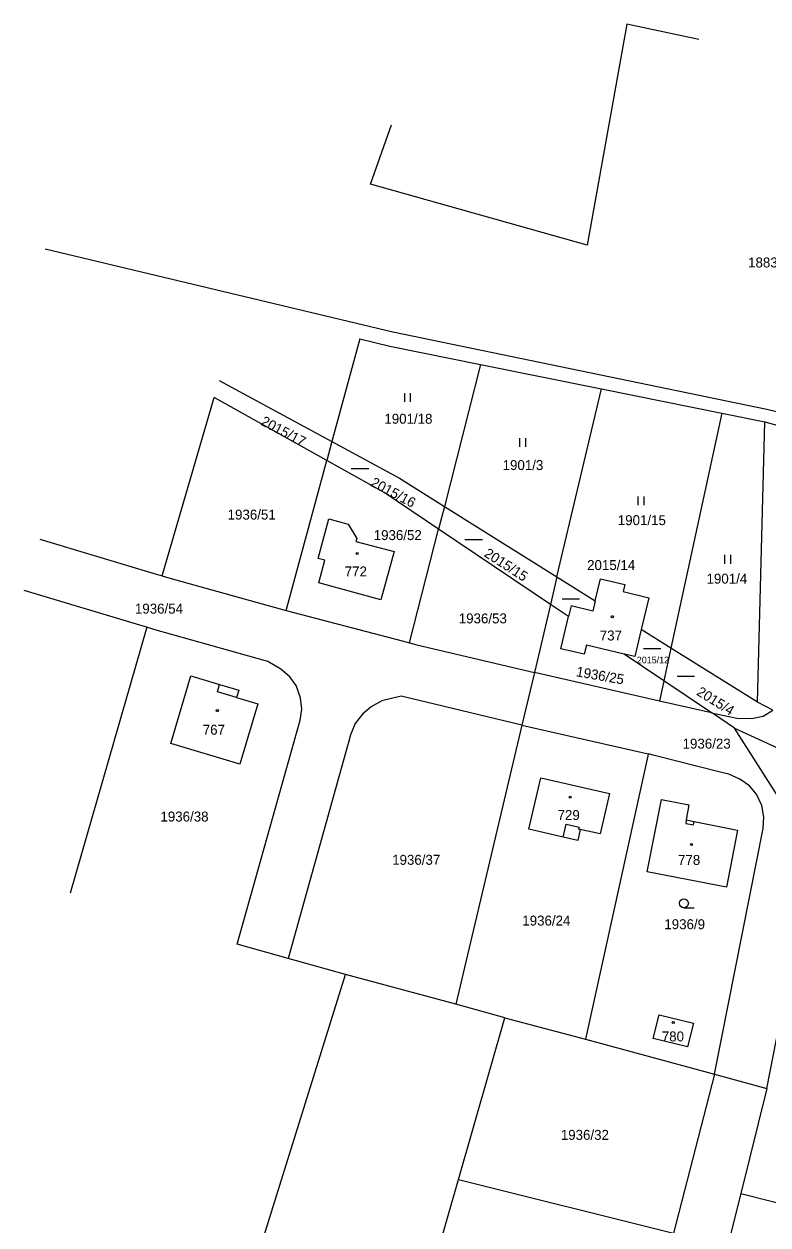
# Model space of a CAD drawing. Extents: x -793666 to -785424, y -1118958 to -1108761.
# Drawn here: x -788618 to -788490.9, y -1116664.5 to -1116459.4 of the extents above; entities that cross this region are included whole.
import ezdxf

# ---------------------------------------------------------------- set-up
doc = ezdxf.new("R2010")
doc.units = 0
for name, color, linetype in [('Hranice parcel', 7, 'Continuous'), ('Parcelní čísla', 7, 'Continuous'), ('Vnitřní kresba', 7, 'Continuous'), ('Značky budov', 7, 'Continuous'), ('Značky kultur', 7, 'Continuous')]:
    doc.layers.add(name, color=color, linetype=linetype)

msp = doc.modelspace()

# ---------------------------------------------------------------- linework, layer by layer
at = {"layer": 'Hranice parcel'}
for p, q in [((-788560.67, -1116513.12), (-788565.43, -1116530.67)), ((-788540.02, -1116517.5), (-788546.21, -1116541.74)), ((-788540.02, -1116517.5), (-788519.4, -1116521.68)), ((-788584.68, -1116520.22), (-788565.43, -1116530.67)), ((-788594.39, -1116553.63), (-788585.54, -1116523.16)), ((-788566.3, -1116533.9), (-788585.54, -1116523.16)), ((-788526.98, -1116553.77), (-788519.4, -1116521.68)), ((-788519.4, -1116521.68), (-788498.83, -1116525.84)), ((-788498.83, -1116525.84), (-788507.51, -1116565.95)), ((-788498.83, -1116525.84), (-788491.48, -1116527.33)), ((-788492.74, -1116575.19), (-788491.48, -1116527.33)), ((-788491.48, -1116527.33), (-788478.73, -1116530.8)), ((-788565.43, -1116530.67), (-788566.3, -1116533.9)), ((-788573.26, -1116559.54), (-788566.3, -1116533.9)), ((-788546.21, -1116541.74), (-788547.2, -1116545.62)), ((-788546.21, -1116541.74), (-788526.98, -1116553.77)), ((-788552.16, -1116565.07), (-788547.2, -1116545.62)), ((-788528.09, -1116558.48), (-788547.2, -1116545.62)), ((-788526.98, -1116553.77), (-788528.09, -1116558.48)), ((-788526.98, -1116553.77), (-788520.44, -1116557.86)), ((-788520.44, -1116557.86), (-788519.55, -1116554.11)), ((-788520.44, -1116557.86), (-788520.86, -1116559.64)), ((-788511.28, -1116557.35), (-788512.57, -1116562.78)), ((-788528.09, -1116558.48), (-788530.84, -1116570.12)), ((-788524.99, -1116560.57), (-788528.09, -1116558.48)), ((-788524.56, -1116558.76), (-788524.99, -1116560.57)), ((-788520.86, -1116559.64), (-788524.56, -1116558.76)), ((-788597.04, -1116562.39), (-788610.11, -1116607.83)), ((-788526.29, -1116566.06), (-788524.99, -1116560.57)), ((-788507.51, -1116565.95), (-788512.57, -1116562.78)), ((-788552.16, -1116565.07), (-788550.89, -1116565.39)), ((-788550.89, -1116565.39), (-788530.84, -1116570.12)), ((-788515.48, -1116566.97), (-788521.93, -1116565.45)), ((-788507.51, -1116565.95), (-788508.72, -1116571.52)), ((-788492.74, -1116575.19), (-788507.51, -1116565.95)), ((-788508.72, -1116571.52), (-788515.48, -1116566.97)), ((-788530.84, -1116570.12), (-788532.99, -1116579.1)), ((-788509.48, -1116575.03), (-788530.84, -1116570.12)), ((-788508.72, -1116571.52), (-788509.48, -1116575.03)), ((-788500.6, -1116576.98), (-788508.72, -1116571.52)), ((-788532.99, -1116579.1), (-788553.61, -1116574.15)), ((-788500.6, -1116576.98), (-788509.48, -1116575.03)), ((-788490.08, -1116576.56), (-788492.74, -1116575.19)), ((-788581.59, -1116616.5), (-788570.85, -1116578.24)), ((-788532.99, -1116579.1), (-788544.24, -1116626.74)), ((-788532.99, -1116579.1), (-788511.4, -1116584.01)), ((-788496.63, -1116579.65), (-788467.26, -1116593.19)), ((-788562.77, -1116582.62), (-788572.92, -1116618.95)), ((-788572.92, -1116618.95), (-788581.59, -1116616.5)), ((-788563.08, -1116621.72), (-788572.92, -1116618.95)), ((-788577.03, -1116666.42), (-788563.08, -1116621.72)), ((-788544.24, -1116626.74), (-788563.08, -1116621.72)), ((-788535.86, -1116629.08), (-788544.24, -1116626.74)), ((-788543.79, -1116656.69), (-788535.86, -1116629.08)), ((-788535.86, -1116629.08), (-788522.1, -1116632.76)), ((-788491.13, -1116641.15), (-788488.9, -1116629.83)), ((-788522.1, -1116632.76), (-788500.05, -1116638.73)), ((-788500.05, -1116638.73), (-788507.06, -1116665.88)), ((-788500.05, -1116638.73), (-788491.13, -1116641.15)), ((-788491.13, -1116641.15), (-788495.6, -1116659.1)), ((-788543.79, -1116656.69), (-788507.06, -1116665.88)), ((-788495.6, -1116659.1), (-788503.37, -1116690.19)), ((-788495.6, -1116659.1), (-788461.96, -1116667.65))]:
    msp.add_line(p, q, dxfattribs=at)
for points in [[(-788502.75, -1116462.02), (-788515.05, -1116459.36), (-788521.83, -1116497.13), (-788558.85, -1116486.73), (-788555.25, -1116476.56)], [(-788614.4, -1116497.78), (-788554.99, -1116511.96), (-788491.11, -1116525.14), (-788431.6, -1116539.59), (-788422.48, -1116487.78), (-788421.23, -1116481.16)], [(-788560.67, -1116513.12), (-788555.5, -1116514.37), (-788540.02, -1116517.5)], [(-788565.43, -1116530.67), (-788553.9, -1116536.93), (-788546.21, -1116541.74)], [(-788547.2, -1116545.62), (-788556.49, -1116539.37), (-788566.3, -1116533.9)], [(-788557.04, -1116557.73), (-788567.66, -1116554.83), (-788566.62, -1116550.96), (-788567.78, -1116550.64), (-788565.96, -1116543.87), (-788562.63, -1116544.76), (-788561.18, -1116547.23), (-788561.31, -1116547.72), (-788554.79, -1116549.48), (-788557.04, -1116557.73)], [(-788615.31, -1116547.34), (-788595.62, -1116553.25), (-788594.39, -1116553.63)], [(-788594.39, -1116553.63), (-788593.12, -1116553.99), (-788573.26, -1116559.54)], [(-788519.55, -1116554.11), (-788515.36, -1116555.09), (-788515.66, -1116556.31), (-788511.28, -1116557.35)], [(-788597.04, -1116562.39), (-788598.23, -1116562.05), (-788618.01, -1116556.14)], [(-788573.26, -1116559.54), (-788553.42, -1116564.71), (-788552.16, -1116565.07)], [(-788570.85, -1116578.24), (-788570.53, -1116576.36), (-788570.78, -1116574.42), (-788571.54, -1116572.32), (-788572.6, -1116570.86), (-788574.15, -1116569.54), (-788576.39, -1116568.22), (-788595.82, -1116562.78), (-788597.04, -1116562.39)], [(-788512.57, -1116562.78), (-788513.67, -1116567.39), (-788515.48, -1116566.97)], [(-788521.93, -1116565.45), (-788522.32, -1116566.97), (-788526.29, -1116566.06)], [(-788581.34, -1116573.13), (-788581.71, -1116574.39), (-788578.07, -1116575.46), (-788581.13, -1116585.75), (-788592.93, -1116582.23), (-788589.49, -1116570.7), (-788584.6, -1116572.16), (-788581.34, -1116573.13)], [(-788553.61, -1116574.15), (-788556.91, -1116574.96), (-788558.72, -1116575.97), (-788560.21, -1116577.21), (-788561.43, -1116578.84), (-788562.26, -1116580.78), (-788562.61, -1116582.09), (-788562.77, -1116582.62)], [(-788500.6, -1116576.98), (-788496.27, -1116577.93), (-788493.73, -1116577.98), (-788491.73, -1116577.56), (-788490.08, -1116576.56)], [(-788496.63, -1116579.65), (-788500.44, -1116577.09), (-788500.6, -1116576.98)], [(-788482.78, -1116598.82), (-788485.13, -1116597.68), (-788496.63, -1116579.65)], [(-788511.4, -1116584.01), (-788511.48, -1116584.37), (-788511.59, -1116584.86), (-788522.1, -1116632.76)], [(-788500.05, -1116638.73), (-788491.76, -1116596.75), (-788491.63, -1116594.82), (-788492, -1116592.84), (-788492.88, -1116590.91), (-788494.12, -1116589.5), (-788495.75, -1116588.32), (-788497.65, -1116587.48), (-788498.89, -1116587.17), (-788510.3, -1116584.29), (-788511.4, -1116584.01)], [(-788525.93, -1116598.22), (-788531.76, -1116596.9), (-788529.74, -1116588.11), (-788518.03, -1116590.78), (-788519.6, -1116597.67), (-788523.01, -1116596.92), (-788523.43, -1116598.8), (-788525.93, -1116598.22)], [(-788509.12, -1116591.81), (-788504.43, -1116592.71), (-788504.89, -1116595.31), (-788503.54, -1116595.57), (-788496.14, -1116597.02), (-788498.02, -1116606.81), (-788511.59, -1116604.18), (-788509.12, -1116591.81)], [(-788509.53, -1116628.58), (-788503.67, -1116630.02), (-788504.67, -1116634.08), (-788510.52, -1116632.64), (-788509.53, -1116628.58)], [(-788549.6, -1116684.41), (-788548.02, -1116671.4), (-788543.79, -1116656.69)]]:
    msp.add_lwpolyline(points, dxfattribs=at)
at = {"layer": 'Vnitřní kresba'}
for p, q in [((-788584.97, -1116573.4), (-788584.6, -1116572.16)), ((-788581.71, -1116574.39), (-788584.97, -1116573.4)), ((-788504.89, -1116595.31), (-788504.99, -1116595.89)), ((-788525.93, -1116598.22), (-788525.42, -1116596)), ((-788525.42, -1116596), (-788523.19, -1116596.52)), ((-788523.19, -1116596.52), (-788523.28, -1116596.87)), ((-788523.28, -1116596.87), (-788523.01, -1116596.92)), ((-788504.99, -1116595.89), (-788503.66, -1116596.15)), ((-788503.66, -1116596.15), (-788503.54, -1116595.57))]:
    msp.add_line(p, q, dxfattribs=at)
at = {"layer": 'Značky budov'}
for centre in [(-788561.12, -1116549.8), (-788517.52, -1116560.59), (-788584.99, -1116576.63), (-788524.74, -1116591.4), (-788504, -1116599.51), (-788507.11, -1116629.89)]:
    msp.add_circle(centre, 0.175, dxfattribs=at)
at = {"layer": 'Značky kultur'}
for p, q in [((-788552.99, -1116523.89), (-788552.99, -1116522.39)), ((-788551.99, -1116523.89), (-788551.99, -1116522.39)), ((-788533.3, -1116531.59), (-788533.3, -1116530.09)), ((-788532.3, -1116531.59), (-788532.3, -1116530.09)), ((-788562.13, -1116535.28), (-788559.13, -1116535.28)), ((-788513.11, -1116541.53), (-788513.11, -1116540.03)), ((-788512.11, -1116541.53), (-788512.11, -1116540.03)), ((-788542.71, -1116547.38), (-788539.71, -1116547.38)), ((-788498.3, -1116551.54), (-788498.3, -1116550.04)), ((-788497.3, -1116551.54), (-788497.3, -1116550.04)), ((-788526.11, -1116557.56), (-788523.11, -1116557.56)), ((-788512.22, -1116566), (-788509.22, -1116566)), ((-788506.46, -1116570.74), (-788503.46, -1116570.74)), ((-788505.29, -1116610.29), (-788503.54, -1116610.29))]:
    msp.add_line(p, q, dxfattribs=at)
msp.add_circle((-788505.29, -1116609.54), 0.75, dxfattribs=at)

# ---------------------------------------------------------------- texts
at = {"layer": 'Parcelní čísla'}
for s, height, p in [('1883/18', 1.7, (-788494.33, -1116500.94)), ('1901/18', 1.7, (-788556.46, -1116527.63)), ('1901/3', 1.7, (-788536.26, -1116535.54)), ('1936/51', 1.7, (-788583.23, -1116544)), ('1901/15', 1.7, (-788516.59, -1116544.95)), ('1936/52', 1.7, (-788558.28, -1116547.5)), ('772', 1.7, (-788563.23, -1116553.71)), ('2015/14', 1.7, (-788521.83, -1116552.62)), ('1901/4', 1.7, (-788501.43, -1116554.94)), ('1936/54', 1.7, (-788599.07, -1116560.06)), ('1936/53', 1.7, (-788543.75, -1116561.73)), ('737', 1.7, (-788519.67, -1116564.65)), ('2015/12', 1.14, (-788513.34, -1116568.55)), ('767', 1.7, (-788587.48, -1116580.75)), ('1936/23', 1.7, (-788505.52, -1116583.12)), ('1936/38', 1.7, (-788594.71, -1116595.57)), ('729', 1.7, (-788526.88, -1116595.31)), ('1936/37', 1.7, (-788555.13, -1116602.96)), ('778', 1.7, (-788506.3, -1116602.98)), ('1936/24', 1.7, (-788532.9, -1116613.34)), ('1936/9', 1.7, (-788508.64, -1116613.96)), ('780', 1.7, (-788509.07, -1116633.13)), ('1936/32', 1.7, (-788526.32, -1116649.94))]:
    msp.add_text(s, height=height, dxfattribs=at).set_placement(p)
for s, rotation, p in [('2015/17', 332, (-788577.72, -1116527.73)), ('2015/16', 332, (-788558.96, -1116538.17)), ('2015/15', 327, (-788539.57, -1116550.18)), ('1936/25', 350, (-788523.79, -1116570.75)), ('2015/4', 328, (-788503.27, -1116573.85))]:
    msp.add_text(s, height=1.7, rotation=rotation, dxfattribs=at).set_placement(p)

doc.saveas('drawing.dxf')
